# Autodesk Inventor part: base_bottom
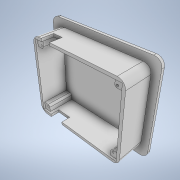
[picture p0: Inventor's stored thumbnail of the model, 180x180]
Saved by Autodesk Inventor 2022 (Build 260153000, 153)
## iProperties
Created: 2022-12
Part Number: base_bottom
Material: Generic
Document SubType Name: Modeling
Designer: suerfu
Density: 1 g/cm^3
Appearance: Default
Author: suerfu
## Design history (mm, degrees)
sketch "Sketch1"
  geometry: L1 (-38.1, 30.48)-(38.1, 30.48); L2 (38.1, 30.48)-(38.1, -30.48); L3 (38.1, -30.48)-(-38.1, -30.48); L4 (-38.1, -30.48)-(-38.1, 30.48); L5 (-89.47, 0)-(54.289, 0); L6 (0, 41.577)-(0, -55.26); L7 (-47.625, 40.005)-(47.625, 40.005); L8 (47.625, 40.005)-(47.625, -40.005); L9 (47.625, -40.005)-(-47.625, -40.005); L10 (-47.625, -40.005)-(-47.625, 40.005); 1 further point
  constraints: 20 end point, 4 parallel, 3 horizontal, 2 perpendicular, 2 point on line, 1 vertical, 1 other
  dimensions: "d0" = 76.2 distance of L2.end L3.end; "d1" = 60.96 distance of L3.end L1.start; "d29" = 9.525 distance between parallel lines of L1 L7; "d30" = 9.525 distance between parallel lines of L8 L2 (= d29); "d31" = 9.525 distance between parallel lines of L10 L4 (= d30); "d32" = 9.525 distance between parallel lines of L9 L3 (= d30); "d33" = 30.48 distance between parallel lines of L5 L1 (= 0.5 x d1)
extrude "Extrusion1" new body sketch "Sketch1" distance "d26" = 2.54; taper "d27" = 0 deg
sketch "Sketch2"
  geometry: L1 (-38.735, 31.115)-(38.735, 31.115); L2 (38.735, 31.115)-(38.735, -31.115); L3 (38.735, -31.115)-(-38.735, -31.115); L4 (-38.735, -31.115)-(-38.735, 31.115); L5 (-41.275, 33.655)-(41.275, 33.655); L6 (41.275, 33.655)-(41.275, -33.655); L7 (41.275, -33.655)-(-41.275, -33.655); L8 (-41.275, -33.655)-(-41.275, 33.655); 1 further point
  constraints: 16 end point, 4 parallel, 2 horizontal, 2 perpendicular
  dimensions: "d34" = 77.47 distance of L1.start L1.end; "d35" = 62.23 distance of L3.end L1.start; "d36" = 31.115 distance from line of point (0, 0) L1 (= 0.5 x d35); "d37" = 38.735 distance from line of point (0, 0) L4 (= 0.5 x d34); "d38" = 2.54 distance between parallel lines of L1 L5; "d39" = 2.54 distance between parallel lines of L6 L2 (= d38); "d40" = 2.54 distance between parallel lines of L7 L3 (= d38); "d41" = 2.54 distance between parallel lines of L4 L8 (= d40)
extrude "Extrusion2" join sketch "Sketch2" distance "d42" = 23.1775; taper "d43" = 0 deg
sketch "Sketch3"
  geometry: L1 (-38.735, 31.115)-(-38.735, -31.115) reference; L2 (-38.735, 31.115)-(38.735, 31.115); L3 (38.735, 31.115)-(38.735, -31.115); L4 (38.735, -31.115)-(-38.735, -31.115); L5 (-38.735, -31.115)-(-38.735, 31.115); 2 further points
  constraints: 8 end point, 2 parallel, 1 horizontal, 1 perpendicular
extrude "Extrusion3" cut sketch "Sketch3" distance "d44" = 1.6256; taper "d45" = 0 deg
sketch "Sketch4"
  geometry: L1 (-38.1, 30.48)-(38.1, 30.48); L2 (38.1, 30.48)-(38.1, -30.48); L3 (38.1, -30.48)-(-38.1, -30.48); L4 (-38.1, -30.48)-(-38.1, 30.48); L5 (-32.385, 26.67)-(-32.385, 31.115); L6 (-38.735, 31.115)-(38.735, 31.115) reference; L7 (-34.29, 24.765)-(-38.735, 24.765); L8 (-38.735, -31.115)-(-38.735, 31.115) reference; L9 (32.385, 26.67)-(32.385, 31.115); L10 (34.29, 24.765)-(38.735, 24.765); L11 (32.385, -26.67)-(32.385, -31.115); L12 (38.735, -24.765)-(34.29, -24.765); L13 (-38.1, -24.765)-(-34.29, -24.765); L14 (-32.385, -26.67)-(-32.385, -30.48); L15 (38.735, 31.115)-(38.735, -31.115) reference; L16 (38.735, -31.115)-(-38.735, -31.115) reference; L17 (-32.385, -30.48)-(-32.385, -31.115); L18 (38.735, -31.115)-(-38.735, -31.115) reference; L19 (-38.1, -24.765)-(-38.735, -24.765); L20 (-38.735, -31.115)-(-38.735, 31.115) reference; A1 r 1.905 centre (-34.29, 26.67) between (-32.385, 26.67) and (-34.29, 24.765); A2 r 1.905 centre (34.29, 26.67) between (34.29, 24.765) and (32.385, 26.67); A3 r 1.905 centre (34.29, -26.67) between (34.29, -24.765) and (32.385, -26.67); A4 r 1.905 centre (-34.29, -26.67) between (-32.385, -26.67) and (-34.29, -24.765); 3 further points
  constraints: 28 end point, 10 point on line, 8 point on circle, 8 tangent, 5 horizontal, 4 centre point, 4 vertical, 3 perpendicular, 2 horizontal alignment, 2 parallel, 2 vertical alignment
  dimensions: "d46" = 76.2 distance of L1.start L1.end; "d47" = 60.96 distance of L3.end L1.start; "d48" = 30.48 distance from line of point (0, 0) L1 (= 0.5 x d47); "d49" = 38.1 distance from line of point (0, 0) L4 (= 0.5 x d46); "d50" = 3.81 diameter of A1; "d51" = 3.81 diameter of A2 (= d50); "d52" = 3.81 diameter of A3 (= d51); "d53" = 3.81 diameter of A4 (= d52); "d54" = 68.58 distance of A2.centre A1.centre; "d55" = 34.29 horizontal distance of point (0, 0) A1.centre (= 0.5 x d54); "d56" = 53.34 distance of A4.centre A1.centre; "d57" = 26.67 vertical distance of point (0, 0) A1.centre (= 0.5 x d56)
extrude "Extrusion4" join sketch "Sketch4" distance "d58" = 23.1902; taper "d59" = 0 deg
sketch "Sketch5"
  geometry: L1 (38.735, -31.115)-(-38.735, -31.115) reference; L2 (-41.275, -33.655)-(41.275, -33.655) reference; L3 (-29.464, -31.115)-(-16.129, -31.115); L4 (-16.129, -31.115)-(-16.129, -33.655); L5 (-16.129, -33.655)-(-29.464, -33.655); L6 (-29.464, -33.655)-(-29.464, -31.115); 3 further points
  constraints: 8 end point, 2 parallel, 2 point on line, 1 horizontal, 1 perpendicular
  dimensions: "d60" = 16.129 distance from line of point (0, 0) L4; "d61" = 29.464 distance from line of point (0, 0) L6
extrude "Extrusion5" cut sketch "Sketch5" distance "d62" = 8; taper "d63" = 0 deg
sketch "Sketch6"
  geometry: L1 (41.275, 33.655)-(-41.275, 33.655) reference; L2 (-38.735, 31.115)-(38.735, 31.115) reference; L3 (-31.877, 33.655)-(-22.86, 33.655); L4 (-22.86, 33.655)-(-22.86, 31.115); L5 (-22.86, 31.115)-(-31.877, 31.115); L6 (-31.877, 31.115)-(-31.877, 33.655); 3 further points
  constraints: 8 end point, 2 parallel, 2 point on line, 1 horizontal, 1 perpendicular
  dimensions: "d64" = 22.86 distance from line of point (0, 0) L4; "d65" = 31.877 distance from line of point (0, 0) L6
extrude "Extrusion6" cut sketch "Sketch6" distance "d66" = 10.795; taper "d67" = 0 deg
fillet "Fillet2" dims "d68" = 6.35
workplane "Work Plane1"
sketch "Sketch7"
  geometry: L1 (-36.195, 0)-(-29.845, 0); L2 (29.845, 0)-(36.195, 0); L3 (-41.275, 0)-(41.275, 0) reference; A1 r 3.175 centre (-33.02, 0) between (-36.195, 0) and (-29.845, 0); A2 r 3.175 centre (33.02, 0) between (29.845, 0) and (36.195, 0); 1 further point
  constraints: 4 end point, 4 point on circle, 2 centre point, 2 point on line, 1 collinear, 1 horizontal
  dimensions: "d70" = 6.35 diameter of A1; "d71" = 6.35 diameter of A2 (= d70); "d72" = 66.04 distance of A2.centre A1.centre; "d73" = 33.02 distance of point (0, 0) A1.centre (= 0.5 x d72)
revolve "Revolution1" sketch "Sketch7" stored, may be unused: angle "d74" = 180 deg
workplane "Work Plane2"
sketch "Sketch9"
  geometry: L1 (-36.195, 0)-(36.195, 0); L2 (41.275, 2.54)-(47.625, 2.54) reference; A1 r 3.175 centre (-33.02, 0) between (-36.195, 0) and (-29.845, 0); A2 r 3.175 centre (33.02, 0) between (29.845, 0) and (36.195, 0); 1 further point
  constraints: 4 point on circle, 3 point on line, 2 centre point, 2 end point, 1 horizontal alignment, 1 midpoint, 1 parallel
  dimensions: "d76" = 6.35 diameter of A1; "d77" = 6.35 diameter of A2 (= d76); "d78" = 66.04 distance of A2.centre A1.centre; "d79" = 33.02 distance of point (0, 0) A1.centre (= 0.5 x d78)
revolve "Revolution2" sketch "Sketch9" stored, may be unused: angle "d80" = 180 deg
sketch "Sketch10"
  geometry: 5 further points
  constraints: 2 horizontal alignment, 2 vertical alignment
  dimensions: "d88" = 68.58 distance of point (34.29, 26.67) point (-34.29, 26.67); "d89" = 34.29 horizontal distance of point (0, 0) point (-34.29, 26.67) (= 0.5 x d88); "d90" = 53.34 distance of point (-34.29, -26.67) point (-34.29, 26.67); "d91" = 26.67 vertical distance of point (0, 0) point (-34.29, 26.67) (= 0.5 x d90)
hole "Hole1" sketch "Sketch10" at (-34.29, 26.67), (34.29, 26.67), (-34.29, -26.67), (34.29, -26.67) diameter "d81" = 1.778; stored, may be unused: countersink angle "d85" = 82 deg, drill point angle "d87" = 118 deg; dims "d82" = 5.6896, "d83" = 3.0226, "d84" = 6.35, "d86" = 12.7
body "Solid1"
other parameters: "d69" = 27.94, "d75" = -55.88
